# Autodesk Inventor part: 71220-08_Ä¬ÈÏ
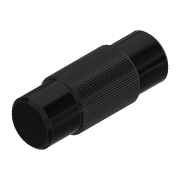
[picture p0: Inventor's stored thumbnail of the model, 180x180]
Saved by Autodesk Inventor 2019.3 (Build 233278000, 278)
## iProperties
Created: 2010-06
Part Number: 71220-08_Ä¬ÈÏ
Material: Ogólny
Document SubType Name: Modeling
Designer: CADENGINEERING4
Density: 1 g/cm^3
Appearance: Gładki — czarny
Author: CADENGINEERING4
Revision Number: ÈÎºÎ
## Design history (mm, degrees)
feature "NONE"
node "Bryła1"
